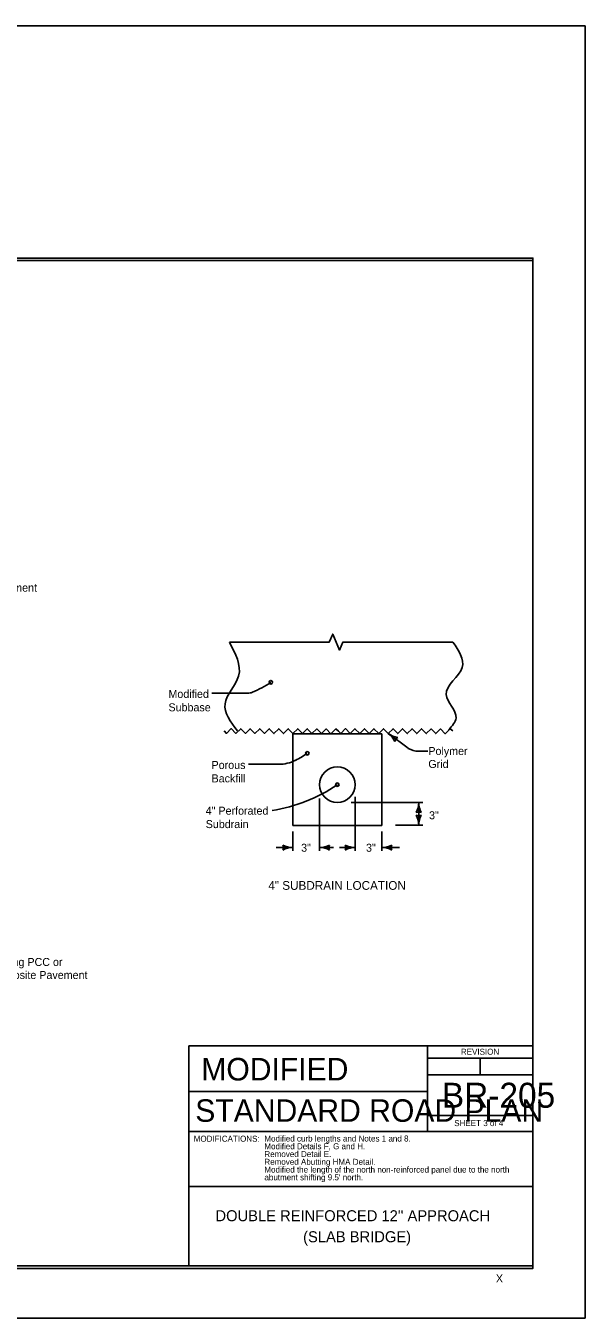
# Model space of a CAD drawing. Extents: x 10028 to 81668, y 6395 to 11634.
# Drawn here: x 23054 to 24172, y 7825 to 10409 of the extents above; entities that cross this region are included whole.
import ezdxf

# ---------------------------------------------------------------- set-up
doc = ezdxf.new("R2010")
doc.units = 0
for name, color, linetype in [('Constructions', 7, 'Continuous'), ('Default', 7, 'Continuous'), ('dsnCellElements', 7, 'Continuous'), ('dsnstdblockInterim', 7, 'Continuous'), ('dsnStdBlockNotModified', 7, 'Continuous'), ('dsnStdDimension', 7, 'Continuous'), ('dsnStgShadingPropPav', 7, 'Continuous'), ('dsnTextNote', 7, 'Continuous'), ('ShtPlotIdentification', 7, 'Continuous'), ('TextAlignmentSml', 7, 'Continuous')]:
    doc.layers.add(name, color=color, linetype=linetype)

msp = doc.modelspace()

# ---------------------------------------------------------------- linework, layer by layer
at = {"layer": 'Default'}
msp.add_lwpolyline([(20932.5, 9944), (24067.5, 9944), (24067.5, 7924), (20932.5, 7924)], close=True, dxfattribs=at)
at = {"layer": 'dsnCellElements'}
for p, q in [((23818.4, 8963.9), (23778.6, 8993.7)), ((23839, 8958.1), (23857.3, 8958.1)), ((23641, 8863.7), (23641, 8759)), ((23712.3, 8867.1), (23712.3, 8759)), ((23704, 8855.5), (23847.5, 8855.5)), ((23839.3, 8855.5), (23839.3, 8810)), ((23587.5, 8797.6), (23587.5, 8759)), ((23765.7, 8797.6), (23765.7, 8759)), ((23793.1, 8810), (23847.5, 8810)), ((23554.2, 8765.6), (23587.5, 8765.6)), ((23641, 8765.6), (23668.9, 8765.6)), ((23681.2, 8765.6), (23712.3, 8765.6)), ((23765.7, 8765.6), (23800.9, 8765.6))]:
    msp.add_line(p, q, dxfattribs=at)
msp.add_arc((23839, 8997.7), 39.6, 238.7046, 270, dxfattribs=at)
at = {"layer": 'dsnstdblockInterim'}
msp.add_lwpolyline([(20932.5, 9939), (24067.5, 9939), (24067.5, 7929), (20932.5, 7929)], close=True, dxfattribs=at)
at = {"layer": 'dsnStdBlockNotModified'}
for centre, radius, start, end in [((23753.1, 8959.6), 42.5, 25.1788, 53.2513), ((23804, 9027.7), 42.5, 233.2513, 261.3238), ((23807.1, 8972.3), 16.4, 125.5179, 160.9846)]:
    msp.add_arc(centre, radius, start, end, dxfattribs=at)
at = {"layer": 'dsnStdDimension'}
msp.add_lwpolyline([(20828, 7824.5), (24172, 7824.5), (24172, 10408.5), (20828, 10408.5)], close=True, dxfattribs=at)
at = {"layer": 'dsnStgShadingPropPav'}
for centre in [(23543.8, 9096), (23616.6, 8953.9), (23676.6, 8891.2)]:
    msp.add_circle(centre, 3.54, dxfattribs=at)
at = {"layer": 'ShtPlotIdentification'}
for p, q in [((23497.3, 9074.1), (23426, 9074.1)), ((23587.5, 8809.6), (23587.5, 8993)), ((23587.5, 8993), (23765.7, 8993)), ((23599.3, 8993), (23765.7, 8993)), ((23765.7, 8809.6), (23765.7, 8993)), ((23559.4, 8932), (23498.9, 8932)), ((23587.5, 8809.6), (23765.7, 8809.6))]:
    msp.add_line(p, q, dxfattribs=at)
for points in [[(23460.8, 9176.4), (23660.6, 9176.4), (23667.4, 9192.2), (23674.1, 9176.4)], [(23907.8, 9176.4), (23687.7, 9176.4), (23680.9, 9160.5), (23674.1, 9176.4)], [(23450.1, 8998.6), (23454.8, 8993.8), (23464.3, 9003.3), (23473.8, 8993.7), (23483.4, 9003.2), (23492.8, 8993.7), (23502.3, 9003.2), (23511.8, 8993.6), (23521.4, 9003.1), (23530.8, 8993.6), (23540.4, 9003.1), (23549.9, 8993.5), (23559.4, 9003), (23568.8, 8993.5), (23578.4, 9002.9), (23587.9, 8993.4), (23597.4, 9002.9), (23606.9, 8993.4), (23616.4, 9002.9), (23625.9, 8993.3), (23635.4, 9002.8), (23644.9, 8993.3), (23654.4, 9002.8), (23663.9, 8993.2), (23673.4, 9002.7), (23679.2, 8998.1)], [(23678.6, 8998.6), (23683.4, 8993.8), (23692.9, 9003.3), (23702.4, 8993.7), (23711.9, 9003.2), (23721.4, 8993.7), (23730.9, 9003.2), (23740.4, 8993.6), (23749.9, 9003.1), (23759.4, 8993.6), (23768.9, 9003.1), (23778.4, 8993.5), (23788, 9003), (23797.4, 8993.5), (23807, 9002.9), (23816.4, 8993.4), (23825.9, 9002.9), (23835.4, 8993.4), (23845, 9002.9), (23854.4, 8993.3), (23864, 9002.8), (23873.4, 8993.3), (23883, 9002.8), (23892.5, 8993.2), (23902, 9002.7), (23907.2, 8998.6)]]:
    msp.add_lwpolyline(points, dxfattribs=at)
msp.add_circle((23676.6, 8891.2), 35.6, dxfattribs=at)
for centre, radius, start, end in [((23430.3, 9261.7), 200.9, 292.4048, 304.4007), ((23497.3, 9099.1), 25, 270, 292.4048), ((23503.1, 9119.6), 200.9, 296.5518, 304.4007), ((23559.4, 9007), 75, 270, 296.5518), ((23499, 9150.6), 314.4, 278.602, 304.4007), ((23796.8, 8855.5), 42.5, 331.9275, 360), ((23881.8, 8855.5), 42.5, 180, 208.0725), ((23839.3, 8819.9), 16.4, 72.2666, 107.7334), ((23839.3, 8845.6), 16.4, 252.2666, 287.7333), ((23796.8, 8810), 42.5, 360, 28.0725), ((23881.8, 8810), 42.5, 151.9275, 180), ((23551.9, 8765.6), 16.4, 342.2666, 17.7333), ((23587.5, 8808.1), 42.5, 241.9275, 270), ((23587.5, 8723.1), 42.5, 90, 118.0725), ((23641, 8808.1), 42.5, 270, 298.0725), ((23641, 8808.1), 42.5, 270, 298.0725), ((23641, 8723.1), 42.5, 61.9275, 90), ((23641, 8723.1), 42.5, 61.9275, 90), ((23676.6, 8765.6), 16.4, 162.2666, 197.7334), ((23676.6, 8765.6), 16.4, 162.2666, 197.7334), ((23676.6, 8765.6), 16.4, 342.2666, 17.7333), ((23712.3, 8808.1), 42.5, 241.9275, 270), ((23676.6, 8765.6), 16.4, 342.2666, 17.7333), ((23712.3, 8808.1), 42.5, 241.9275, 270), ((23712.3, 8723.1), 42.5, 90, 118.0725), ((23712.3, 8723.1), 42.5, 90, 118.0725), ((23765.7, 8808.1), 42.5, 270, 298.0725), ((23765.7, 8723.1), 42.5, 61.9275, 90), ((23801.4, 8765.6), 16.4, 162.2666, 197.7334)]:
    msp.add_arc(centre, radius, start, end, dxfattribs=at)
for points in [[(23460.8, 9176.4), (23479.3, 9108.5), (23452.1, 9052.9), (23476.8, 8998.6)], [(23907.8, 9176.4), (23926.3, 9125.8), (23894.2, 9071.5), (23914, 9024.5), (23899.1, 9001)]]:
    msp.add_spline(points, degree=3, dxfattribs=at)
at = {"layer": 'TextAlignmentSml'}
for p, q in [((23856.6, 8369), (23856.6, 8277.7)), ((23856.6, 8344.1), (24067.5, 8344.1)), ((23962.1, 8344.1), (23962.1, 8310.9)), ((23856.6, 8310.9), (24067.5, 8310.9)), ((23379.5, 8277.7), (23856.6, 8277.7)), ((23856.6, 8277.7), (23856.6, 8197.7)), ((24067.5, 8229.9), (23856.6, 8229.9)), ((23379.5, 8197.7), (24067.5, 8197.7)), ((23379.5, 8087.7), (24067.5, 8087.7))]:
    msp.add_line(p, q, dxfattribs=at)
msp.add_lwpolyline([(23379.5, 8369), (24067.5, 8369), (24067.5, 7929), (23379.5, 7929)], close=True, dxfattribs=at)

# ---------------------------------------------------------------- texts
at = {"layer": 'Constructions'}
msp.add_text('X', height=16, dxfattribs=at).set_placement((23993.6, 7896))
at = {"layer": 'dsnCellElements'}
for s, p in [('Composite Pavement', (22871.7, 9277.2)), ('Modified', (23339, 9064.7)), ('Subbase', (23339, 9037.9)), ('Polymer ', (23858.6, 8950.6)), ('Grid', (23858.6, 8924.6)), ('Porous', (23425.2, 8922.6)), ('Backfill', (23425.2, 8895.8)), ('4" Perforated ', (23413.5, 8831.2)), ('3"', (23860, 8822.1)), ('Subdrain', (23413.5, 8804.4)), ('3"', (23604.2, 8757.1)), ('3"', (23734, 8757.1)), ('Abutting PCC or', (22972.6, 8528.7)), ('Composite Pavement', (22972.6, 8502.7))]:
    msp.add_text(s, height=16, dxfattribs=at).set_placement(p)
at = {"layer": 'dsnTextNote'}
for s, height, p in [('MODIFIED', 45, (23404.6, 8299.8)), ('MODIFICATIONS:', 12, (23389.5, 8177.3))]:
    msp.add_text(s, height=height, dxfattribs=at).set_placement(p)
at = {"layer": 'ShtPlotIdentification'}
msp.add_text('4" SUBDRAIN LOCATION', height=17.5, dxfattribs=at).set_placement((23538.7, 8681))
at = {"layer": 'TextAlignmentSml'}
for s, height, p in [('REVISION', 12, (23923.6, 8351.2)), ('BR-205', 50, (23885.5, 8245.2)), ('STANDARD ROAD PLAN', 45.001, (23392.6, 8217.1)), ('SHEET 3 of 4', 12, (23910.3, 8208.5)), ('Modified curb lengths and Notes 1 and 8.', 12, (23530.8, 8177.7)), ('Modified Details F, G and H.', 12, (23530.8, 8162.2)), ('Removed Detail E.', 12, (23530.8, 8146.6)), ('Removed Abutting HMA Detail.', 12, (23530.8, 8131.1)), ('Modified the length of the north non-reinforced panel due to the north', 12, (23530.8, 8115.6)), ("abutment shifting 9.5' north.", 12, (23530.8, 8100.1)), ("DOUBLE REINFORCED 12'' APPROACH", 22, (23433, 8018.3)), ('(SLAB BRIDGE)', 22, (23608.2, 7976.3))]:
    msp.add_text(s, height=height, dxfattribs=at).set_placement(p)

doc.saveas('drawing.dxf')
